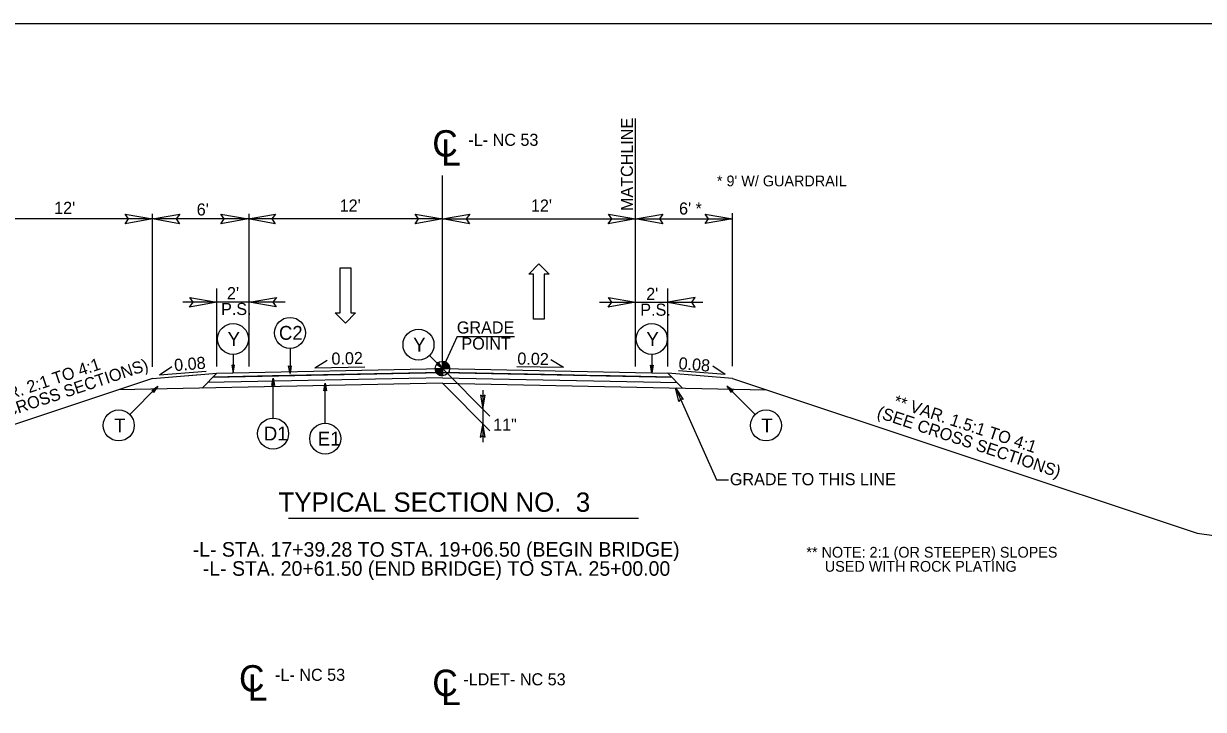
# Model space of a CAD drawing. Extents: x 1548135 to 1549339, y 868664 to 869085.
# Drawn here: x 1548194.7 to 1548268, y 868869.2 to 868911.8 of the extents above; entities that cross this region are included whole.
import ezdxf

# ---------------------------------------------------------------- set-up
doc = ezdxf.new("R2010")
doc.units = 0
for name, color, linetype in [('Default', 7, 'Continuous'), ('P_RDY_TC_Pvmt_Asphalt_Base_Course', 7, 'Continuous'), ('Prop Dimension', 7, 'Continuous'), ('Prop Dimension Text', 7, 'Continuous'), ('Prop Terminator CELL', 7, 'Continuous'), ('Sheet_Data_Field_CELL', 7, 'Continuous'), ('Sheet_Plan', 7, 'Continuous'), ('Sheet_Title_Block_Text', 7, 'Continuous'), ('Typical Curb CELL', 7, 'Continuous'), ('Typical Grade Point Symbol CELL', 7, 'Continuous'), ('Typical Hinge Slope Arterial CELL', 7, 'Continuous'), ('Typical Hinge Slope Interstate CELL', 7, 'Continuous'), ('Typical Pavement Slope CELL', 7, 'Continuous'), ('Typical Pavement Slope Information CELL', 7, 'Continuous'), ('Typical Shoulder Slope CELL', 7, 'Continuous'), ('Typical Shoulder Slope Information CELL', 7, 'Continuous'), ('Typical Terminator CELL', 7, 'Continuous'), ('Typical Text Centerline CELL', 7, 'Continuous'), ('Typical Text General CELL', 7, 'Continuous'), ('Typical Text Grade Point CELL', 7, 'Continuous'), ('z - Construction', 7, 'Continuous')]:
    doc.layers.add(name, color=color, linetype=linetype)

msp = doc.modelspace()

# ---------------------------------------------------------------- linework, layer by layer
at = {"layer": 'Default'}
msp.add_lwpolyline([(1548135.05, 868911.824), (1548305.05, 868911.824), (1548305.05, 868801.824), (1548135.05, 868801.824)], close=True, dxfattribs=at)
at = {"layer": 'P_RDY_TC_Pvmt_Asphalt_Base_Course'}
for points in [[(1548201.05, 868899.982), (1548202.737, 868899.691), (1548201.04, 868899.391), (1548201.256, 868899.691)], [(1548204.425, 868899.4), (1548202.737, 868899.691), (1548204.434, 868899.991), (1548204.219, 868899.691)], [(1548206.99, 868899.982), (1548208.678, 868899.691), (1548206.981, 868899.391), (1548207.197, 868899.691)], [(1548210.365, 868899.4), (1548208.678, 868899.691), (1548210.375, 868899.991), (1548210.159, 868899.691)], [(1548219.05, 868899.982), (1548220.737, 868899.691), (1548219.04, 868899.391), (1548219.256, 868899.691)], [(1548222.425, 868899.4), (1548220.737, 868899.691), (1548222.434, 868899.991), (1548222.219, 868899.691)], [(1548231.05, 868899.982), (1548232.737, 868899.691), (1548231.04, 868899.391), (1548231.256, 868899.691)], [(1548234.425, 868899.4), (1548232.737, 868899.691), (1548234.434, 868899.991), (1548234.219, 868899.691)], [(1548237.061, 868899.999), (1548238.749, 868899.709), (1548237.052, 868899.409), (1548237.267, 868899.709)], [(1548205.05, 868894.808), (1548206.737, 868894.518), (1548205.04, 868894.218), (1548205.256, 868894.518)], [(1548210.425, 868894.227), (1548208.737, 868894.518), (1548210.434, 868894.818), (1548210.219, 868894.518)], [(1548231.05, 868894.808), (1548232.737, 868894.518), (1548231.04, 868894.218), (1548231.256, 868894.518)], [(1548236.425, 868894.808), (1548234.737, 868894.518), (1548236.434, 868894.218), (1548236.219, 868894.518)]]:
    msp.add_lwpolyline(points, close=True, dxfattribs=at)
at = {"layer": 'Prop Dimension'}
msp.add_lwpolyline([(1548267.597, 868880.174), (1548268.634, 868880.045)], dxfattribs=at)
at = {"layer": 'Prop Dimension Text'}
for p, q in [((1548206.487, 868889.869), (1548220.737, 868890.154)), ((1548220.737, 868890.154), (1548234.988, 868889.869))]:
    msp.add_line(p, q, dxfattribs=at)
at = {"layer": 'Prop Terminator CELL'}
msp.add_lwpolyline([(1548206.737, 868890.124), (1548220.737, 868890.404), (1548234.737, 868890.124), (1548234.988, 868889.869), (1548231.155, 868889.946), (1548229.712, 868889.975), (1548228.142, 868890.006), (1548220.737, 868890.154), (1548220.737, 868890.154), (1548210.192, 868889.943), (1548206.487, 868889.869)], close=True, dxfattribs=at)
at = {"layer": 'Sheet_Data_Field_CELL'}
for p, q in [((1548202.737, 868889.791), (1548190.737, 868885.791)), ((1548238.749, 868889.79), (1548267.597, 868880.174))]:
    msp.add_line(p, q, dxfattribs=at)
at = {"layer": 'Sheet_Plan'}
for p, q in [((1548202.737, 868889.791), (1548206.737, 868890.124)), ((1548238.749, 868889.79), (1548234.737, 868890.124))]:
    msp.add_line(p, q, dxfattribs=at)
at = {"layer": 'Typical Curb CELL'}
for p, q in [((1548220.29, 868890.404), (1548220.737, 868890.404)), ((1548220.736, 868889.957), (1548220.737, 868890.404)), ((1548220.737, 868890.404), (1548220.736, 868889.957)), ((1548220.737, 868890.404), (1548220.737, 868890.852)), ((1548221.185, 868890.404), (1548220.737, 868890.404))]:
    msp.add_line(p, q, dxfattribs=at)
for points in [[(1548220.292, 868890.404), (1548220.292, 868890.356)], [(1548220.301, 868890.404), (1548220.301, 868890.303)], [(1548220.31, 868890.404), (1548220.31, 868890.271)], [(1548220.319, 868890.404), (1548220.319, 868890.244)], [(1548220.328, 868890.404), (1548220.328, 868890.223)], [(1548220.336, 868890.404), (1548220.336, 868890.204)], [(1548220.345, 868890.404), (1548220.345, 868890.188)], [(1548220.354, 868890.404), (1548220.354, 868890.172)], [(1548220.363, 868890.404), (1548220.363, 868890.158)], [(1548220.372, 868890.404), (1548220.372, 868890.145)], [(1548220.381, 868890.404), (1548220.381, 868890.133)], [(1548220.39, 868890.404), (1548220.39, 868890.122)], [(1548220.399, 868890.404), (1548220.399, 868890.111)], [(1548220.408, 868890.404), (1548220.408, 868890.101)], [(1548220.417, 868890.404), (1548220.417, 868890.091)], [(1548220.426, 868890.404), (1548220.426, 868890.082)], [(1548220.435, 868890.404), (1548220.435, 868890.074)], [(1548220.444, 868890.404), (1548220.444, 868890.066)], [(1548220.453, 868890.404), (1548220.453, 868890.058)], [(1548220.462, 868890.404), (1548220.462, 868890.051)], [(1548220.471, 868890.404), (1548220.471, 868890.044)], [(1548220.48, 868890.404), (1548220.48, 868890.038)], [(1548220.489, 868890.404), (1548220.489, 868890.032)], [(1548220.498, 868890.404), (1548220.498, 868890.026)], [(1548220.507, 868890.404), (1548220.507, 868890.02)], [(1548220.516, 868890.404), (1548220.516, 868890.015)], [(1548220.524, 868890.404), (1548220.524, 868890.011)], [(1548220.533, 868890.404), (1548220.533, 868890.006)], [(1548220.542, 868890.404), (1548220.542, 868890.002)], [(1548220.551, 868890.404), (1548220.551, 868889.998)], [(1548220.56, 868890.404), (1548220.56, 868889.994)], [(1548220.569, 868890.404), (1548220.569, 868889.99)], [(1548220.578, 868890.404), (1548220.578, 868889.986)], [(1548220.587, 868890.404), (1548220.587, 868889.983)], [(1548220.596, 868890.404), (1548220.596, 868889.98)], [(1548220.605, 868890.404), (1548220.605, 868889.977)], [(1548220.614, 868890.404), (1548220.614, 868889.975)], [(1548220.623, 868890.404), (1548220.623, 868889.972)], [(1548220.632, 868890.404), (1548220.632, 868889.97)], [(1548220.641, 868890.404), (1548220.641, 868889.968)], [(1548220.65, 868890.404), (1548220.65, 868889.966)], [(1548220.659, 868890.404), (1548220.659, 868889.964)], [(1548220.668, 868890.404), (1548220.668, 868889.963)], [(1548220.677, 868890.404), (1548220.677, 868889.961)], [(1548220.686, 868890.404), (1548220.686, 868889.96)], [(1548220.695, 868890.404), (1548220.695, 868889.959)], [(1548220.704, 868890.404), (1548220.704, 868889.958)], [(1548220.712, 868890.404), (1548220.712, 868889.958)], [(1548220.721, 868890.404), (1548220.721, 868889.957)], [(1548220.73, 868890.404), (1548220.73, 868889.957), (1548220.73, 868889.957)], [(1548220.741, 868890.852), (1548220.741, 868890.852), (1548220.741, 868890.404)], [(1548220.75, 868890.852), (1548220.75, 868890.404)], [(1548220.759, 868890.851), (1548220.759, 868890.404)], [(1548220.768, 868890.851), (1548220.768, 868890.404)], [(1548220.777, 868890.85), (1548220.777, 868890.404)], [(1548220.786, 868890.849), (1548220.786, 868890.404)], [(1548220.795, 868890.848), (1548220.795, 868890.404)], [(1548220.804, 868890.847), (1548220.804, 868890.404)], [(1548220.813, 868890.846), (1548220.813, 868890.404)], [(1548220.822, 868890.844), (1548220.822, 868890.404)], [(1548220.831, 868890.842), (1548220.831, 868890.404)], [(1548220.84, 868890.84), (1548220.84, 868890.404)], [(1548220.849, 868890.838), (1548220.849, 868890.404)], [(1548220.858, 868890.835), (1548220.858, 868890.404)], [(1548220.867, 868890.833), (1548220.867, 868890.404)], [(1548220.876, 868890.83), (1548220.876, 868890.404)], [(1548220.885, 868890.827), (1548220.885, 868890.404)], [(1548220.893, 868890.824), (1548220.893, 868890.404)], [(1548220.902, 868890.82), (1548220.902, 868890.404)], [(1548220.911, 868890.816), (1548220.911, 868890.404)], [(1548220.92, 868890.812), (1548220.92, 868890.404)], [(1548220.929, 868890.808), (1548220.929, 868890.404)], [(1548220.938, 868890.804), (1548220.938, 868890.404)], [(1548220.947, 868890.799), (1548220.947, 868890.404)], [(1548220.956, 868890.794), (1548220.956, 868890.404)], [(1548220.965, 868890.789), (1548220.965, 868890.404)], [(1548220.974, 868890.784), (1548220.974, 868890.404)], [(1548220.983, 868890.778), (1548220.983, 868890.404)], [(1548220.992, 868890.772), (1548220.992, 868890.404)], [(1548221.001, 868890.765), (1548221.001, 868890.404)], [(1548221.01, 868890.759), (1548221.01, 868890.404)], [(1548221.019, 868890.752), (1548221.019, 868890.404)], [(1548221.028, 868890.745), (1548221.028, 868890.404)], [(1548221.037, 868890.737), (1548221.037, 868890.404)], [(1548221.046, 868890.729), (1548221.046, 868890.404)], [(1548221.055, 868890.72), (1548221.055, 868890.404)], [(1548221.064, 868890.711), (1548221.064, 868890.404)], [(1548221.073, 868890.701), (1548221.073, 868890.404)], [(1548221.081, 868890.69), (1548221.081, 868890.404)], [(1548221.09, 868890.679), (1548221.09, 868890.404)], [(1548221.099, 868890.667), (1548221.099, 868890.404)], [(1548221.108, 868890.654), (1548221.108, 868890.404)], [(1548221.117, 868890.64), (1548221.117, 868890.404)], [(1548221.126, 868890.625), (1548221.126, 868890.404)], [(1548221.135, 868890.609), (1548221.135, 868890.404)], [(1548221.144, 868890.59), (1548221.144, 868890.404)], [(1548221.153, 868890.569), (1548221.153, 868890.404)], [(1548221.162, 868890.545), (1548221.162, 868890.404)], [(1548221.171, 868890.514), (1548221.171, 868890.404)], [(1548221.18, 868890.468), (1548221.18, 868890.404)]]:
    msp.add_lwpolyline(points, dxfattribs=at)
msp.add_circle((1548220.737, 868890.404), 0.448, dxfattribs=at)
for start, end in [(179.99048, 269.99048), (359.99048, 89.99048)]:
    msp.add_arc((1548220.737, 868890.404), 0.448, start, end, dxfattribs=at)
at = {"layer": 'Typical Grade Point Symbol CELL'}
for p, q in [((1548232.737, 868890.524), (1548232.737, 868905.922)), ((1548220.737, 868890.404), (1548220.737, 868902.397)), ((1548202.737, 868890.505), (1548202.737, 868900.016)), ((1548208.737, 868890.524), (1548208.737, 868900.016)), ((1548238.749, 868890.542), (1548238.749, 868900.054)), ((1548220.737, 868899.691), (1548174.739, 868899.691)), ((1548207.737, 868899.691), (1548205.737, 868899.691)), ((1548220.737, 868899.691), (1548238.749, 868899.691)), ((1548233.737, 868899.691), (1548235.737, 868899.691)), ((1548206.737, 868890.524), (1548206.737, 868895.368)), ((1548234.737, 868890.524), (1548234.737, 868895.368)), ((1548210.987, 868894.518), (1548204.63, 868894.518)), ((1548230.487, 868894.518), (1548236.918, 868894.518))]:
    msp.add_line(p, q, dxfattribs=at)
at = {"layer": 'Typical Hinge Slope Arterial CELL'}
msp.add_line((1548221.661, 868892.391), (1548225.218, 868892.391), dxfattribs=at)
at = {"layer": 'Typical Hinge Slope Interstate CELL'}
for p, q in [((1548207.74, 868891.279), (1548207.74, 868890.144)), ((1548211.277, 868891.658), (1548211.277, 868890.096)), ((1548219.935, 868891.206), (1548220.737, 868890.404)), ((1548233.735, 868891.279), (1548233.735, 868890.144)), ((1548223.689, 868887.453), (1548220.737, 868890.404)), ((1548204.737, 868889.958), (1548206.737, 868890.124)), ((1548206.737, 868890.124), (1548205.819, 868889.189)), ((1548210.227, 868887.329), (1548210.227, 868889.814)), ((1548201.323, 868887.552), (1548203.081, 868889.309)), ((1548213.462, 868887.013), (1548213.462, 868889.498)), ((1548223.69, 868886.536), (1548220.739, 868889.487)), ((1548223.242, 868889.054), (1548223.243, 868885.828)), ((1548240.151, 868887.552), (1548238.393, 868889.309))]:
    msp.add_line(p, q, dxfattribs=at)
for points in [[(1548207.659, 868890.613), (1548207.74, 868890.144), (1548207.823, 868890.616), (1548207.74, 868890.556)], [(1548211.358, 868890.564), (1548211.277, 868890.096), (1548211.194, 868890.567), (1548211.277, 868890.507)], [(1548220.463, 868890.793), (1548220.737, 868890.404), (1548220.345, 868890.679), (1548220.446, 868890.695)], [(1548233.815, 868890.613), (1548233.735, 868890.144), (1548233.651, 868890.616), (1548233.735, 868890.556)], [(1548210.146, 868889.345), (1548210.227, 868889.814), (1548210.31, 868889.343), (1548210.227, 868889.403)], [(1548202.693, 868889.035), (1548203.081, 868889.309), (1548202.807, 868888.917), (1548202.79, 868889.018)], [(1548213.381, 868889.029), (1548213.462, 868889.498), (1548213.545, 868889.027), (1548213.462, 868889.087)], [(1548235.422, 868888.368), (1548235.213, 868889.198), (1548235.694, 868888.483), (1548235.513, 868888.521)], [(1548238.782, 868889.035), (1548238.393, 868889.309), (1548238.668, 868888.917), (1548238.684, 868889.018)], [(1548223.097, 868888.743), (1548223.242, 868887.899), (1548223.392, 868888.748), (1548223.242, 868888.64)], [(1548223.388, 868886.139), (1548223.242, 868886.982), (1548223.092, 868886.134), (1548223.242, 868886.242)]]:
    msp.add_lwpolyline(points, close=True, dxfattribs=at)
msp.add_lwpolyline([(1548235.213, 868889.198), (1548237.746, 868883.488), (1548238.497, 868883.488)], dxfattribs=at)
for centre in [(1548211.277, 868892.619), (1548207.74, 868892.24), (1548219.255, 868891.887), (1548233.735, 868892.24), (1548200.644, 868886.871), (1548240.831, 868886.871), (1548210.227, 868886.367), (1548213.462, 868886.051)]:
    msp.add_circle(centre, 0.962, dxfattribs=at)
at = {"layer": 'Typical Pavement Slope CELL'}
msp.add_line((1548206.737, 868890.124), (1548220.737, 868890.404), dxfattribs=at)
at = {"layer": 'Typical Pavement Slope Information CELL'}
for p, q in [((1548203.185, 868890.007), (1548203.936, 868890.529)), ((1548212.811, 868890.446), (1548213.594, 868890.92)), ((1548212.811, 868890.446), (1548215.933, 868890.509)), ((1548228.258, 868890.462), (1548225.366, 868890.52)), ((1548228.258, 868890.462), (1548227.475, 868890.936)), ((1548238.287, 868890.031), (1548237.535, 868890.553)), ((1548203.185, 868890.007), (1548206.068, 868890.247)), ((1548238.287, 868890.031), (1548235.404, 868890.271))]:
    msp.add_line(p, q, dxfattribs=at)
at = {"layer": 'Typical Shoulder Slope CELL'}
msp.add_line((1548221.661, 868892.391), (1548220.737, 868890.404), dxfattribs=at)
at = {"layer": 'Typical Shoulder Slope Information CELL'}
for p, q in [((1548226.101, 868896.274), (1548226.721, 868896.904)), ((1548226.721, 868896.904), (1548227.361, 868896.274)), ((1548214.384, 868893.86), (1548214.384, 868896.66)), ((1548214.384, 868896.66), (1548215.044, 868896.66)), ((1548215.044, 868896.66), (1548215.044, 868893.86)), ((1548226.401, 868896.274), (1548226.101, 868896.274)), ((1548226.401, 868893.474), (1548226.401, 868896.274)), ((1548227.361, 868896.274), (1548227.061, 868896.274)), ((1548227.061, 868896.274), (1548227.061, 868893.474)), ((1548214.724, 868893.23), (1548214.084, 868893.86)), ((1548214.084, 868893.86), (1548214.384, 868893.86)), ((1548215.344, 868893.86), (1548214.724, 868893.23)), ((1548215.044, 868893.86), (1548215.344, 868893.86)), ((1548227.061, 868893.474), (1548226.401, 868893.474))]:
    msp.add_line(p, q, dxfattribs=at)
at = {"layer": 'Typical Terminator CELL'}
msp.add_line((1548211.185, 868881.106), (1548232.906, 868881.106), dxfattribs=at)
at = {"layer": 'Typical Text Grade Point CELL'}
for p, q in [((1548220.737, 868890.404), (1548234.737, 868890.124)), ((1548220.737, 868889.821), (1548206.153, 868889.529)), ((1548220.737, 868889.821), (1548235.322, 868889.529)), ((1548234.737, 868890.124), (1548235.655, 868889.189)), ((1548220.737, 868889.488), (1548200.62, 868889.085)), ((1548220.737, 868889.488), (1548240.864, 868889.085))]:
    msp.add_line(p, q, dxfattribs=at)

# ---------------------------------------------------------------- texts
at = {"layer": 'Sheet_Data_Field_CELL'}
for s, rotation, p in [('VAR. 2:1 TO 4:1', 18.43497, (1548192.6, 868888.044)), ('(SEE CROSS SECTIONS)', 18.43497, (1548191.238, 868886.554)), ('** VAR. 1.5:1 TO 4:1', 341.56503, (1548248.698, 868888.076)), ('(SEE CROSS SECTIONS)', 341.56503, (1548247.664, 868887.384))]:
    msp.add_text(s, height=0.75, rotation=rotation, dxfattribs=at).set_placement(p)
at = {"layer": 'Sheet_Title_Block_Text'}
for p in [(1548220.11, 868903.565), (1548208.11, 868870.345), (1548220.11, 868870.065)]:
    msp.add_text('C', height=1.64, dxfattribs=at).set_placement(p)
for p in [(1548220.656, 868903.005), (1548208.655, 868869.785), (1548220.655, 868869.505)]:
    msp.add_text('L', height=1.641, rotation=359.9469, dxfattribs=at).set_placement(p)
at = {"layer": 'Typical Hinge Slope Arterial CELL'}
msp.add_text('  TYPICAL SECTION NO.  3', height=1.2, dxfattribs=at).set_placement((1548209.674, 868881.508))
at = {"layer": 'Typical Hinge Slope Interstate CELL'}
msp.add_text('MATCHLINE', height=0.75, rotation=90, dxfattribs=at).set_placement((1548232.568, 868900.182))
for s, height, p in [('-L- NC 53', 0.75, (1548222.352, 868904.233)), ('Y', 0.861, (1548207.403, 868891.81)), ('C2', 0.8608, (1548210.591, 868892.189)), ('Y', 0.861, (1548233.404, 868891.81)), ('Y', 0.861, (1548218.924, 868891.456)), ('T', 0.861, (1548200.361, 868886.441)), ('D1', 0.8608, (1548209.653, 868885.937)), ('11"', 0.75, (1548223.889, 868886.541)), ('T', 0.861, (1548240.54, 868886.441)), ('E1', 0.8608, (1548213.005, 868885.621)), ('GRADE TO THIS LINE', 0.75, (1548238.585, 868883.158)), ('-L- NC 53', 0.75, (1548210.352, 868871.012)), ('-LDET- NC 53', 0.75, (1548222.037, 868870.732))]:
    msp.add_text(s, height=height, dxfattribs=at).set_placement(p)
at = {"layer": 'Typical Pavement Slope Information CELL'}
for rotation, p in [(1.45507, (1548213.861, 868890.641)), (358.85436, (1548225.386, 868890.655))]:
    msp.add_text('0.02', height=0.75, rotation=rotation, dxfattribs=at).set_placement(p)
at = {"layer": 'Typical Shoulder Slope CELL'}
for s, p in [("12'", (1548196.633, 868900.007)), ("6'", (1548205.485, 868899.909)), ("12'", (1548214.36, 868900.152)), ("12'", (1548226.237, 868900.152)), ("6' *", (1548235.43, 868899.966)), ('GRADE', (1548221.636, 868892.58)), ('POINT', (1548221.921, 868891.586))]:
    msp.add_text(s, height=0.75, dxfattribs=at).set_placement(p)
at = {"layer": 'Typical Text Centerline CELL'}
for s, p in [("2'", (1548207.365, 868894.711)), ("2'", (1548233.393, 868894.667)), ('P.S.', (1548206.996, 868893.728)), ('P.S.', (1548233.024, 868893.684))]:
    msp.add_text(s, height=0.75, dxfattribs=at).set_placement(p)
at = {"layer": 'Typical Text General CELL'}
for s, height, p in [("* 9' W/ GUARDRAIL", 0.66824, (1548237.781, 868901.72)), ('-L- STA. 17+39.28 TO STA. 19+06.50 (BEGIN BRIDGE)', 0.90387, (1548205.234, 868878.722)), ('** NOTE: 2:1 (OR STEEPER) SLOPES ', 0.66824, (1548243.335, 868878.663)), ('-L- STA. 20+61.50 (END BRIDGE) TO STA. 25+00.00', 0.90387, (1548205.865, 868877.537)), ('USED WITH ROCK PLATING', 0.66824, (1548244.48, 868877.787))]:
    msp.add_text(s, height=height, dxfattribs=at).set_placement(p)
at = {"layer": 'z - Construction'}
for rotation, p in [(4.76147, (1548204.117, 868890.241)), (355.23853, (1548235.379, 868890.369))]:
    msp.add_text('0.08', height=0.75, rotation=rotation, dxfattribs=at).set_placement(p)

doc.saveas('drawing.dxf')
